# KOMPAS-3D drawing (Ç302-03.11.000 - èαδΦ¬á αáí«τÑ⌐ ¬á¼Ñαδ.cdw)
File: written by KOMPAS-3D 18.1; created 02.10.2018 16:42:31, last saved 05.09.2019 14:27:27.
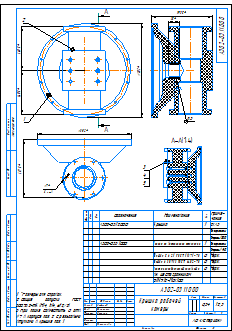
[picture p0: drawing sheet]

Sheet 1: A3, portrait

Document properties: Автор: Милов; Масса: 6.54231; Полное имя файла: ..\А302-01.11.000 - Крышка рабочей камеры.a3d

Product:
- Part/product: (unnamed)
  - Component: Корпус со встроенными стаканами  | designation А302-03.31.000  | pos. 0  | Раздел спецификации: Детали; Примечание: Полипропилен / Стержень @2~140
  - Component: Крышка  | designation А302-03.12.000  | pos. 0  | Раздел спецификации: Детали; Примечание: 2хА3 / Полипропилен / Стержень @2~300
  - Component: Шайба C.6.21 ГОСТ 11371-78  | pos. 0  | Раздел спецификации: Стандартные изделия; Примечание: Нерж.
  - Component: Шайба 6 30Х13 ГОСТ 6402-70  | pos. 0  | Раздел спецификации: Стандартные изделия; Примечание: Нерж.
  - Component: Винт с цилиндрической головкой и  / вн. шестигранником  / DIN 912-М6х100  | pos. 0  | Раздел спецификации: Стандартные изделия; Примечание: Нерж.

Title block, sheet 1: Наименование: Крышка рабочей / камеры; designation: А302-03.11.000; Масса: 6,54; scale: 1:2,5; Количество листов документа: 1; organisation: АО «Астерион»; Форматы листов документа: A3; stored path: \\192.168.87.28\Konstructor_doc\Мембранные насосы\Мембранный электропривод\А302-00.00.000 - ASTRA-302 (МЭ200)\3Д ПВХ\А302-01.11.000 - Крышка рабочей камеры.cdw; Разработал: Лифлянд; Проверил: Борисенко; Т. контр.: Лучихин; Утвердил: Григорьева

Views: Вид 1, Местный разрез 1, Спереди, Проекционный вид 3, Разрез А-А, Вид:1
Referenced files in D:\Мембранные насосы\Мембранный электропривод\А302-00.00.000 - ASTRA-302 (МЭ200)\3Д ПВХ\: А302-01.31.000 - Корпус со встроенными стаканами.m3d, А302-01.12.001 - Крышка.m3d, А302-01.11.000 - Крышка рабочей камеры.a3d, А302-01.12.000 - Крышка.a3d, А302-01.12.000 - Крышка.cdw, А302-01.31.000 - Корпус.a3d, А302-01.31.000 - Корпус.cdw, Втулка резьбовая М6 (шт.) Alutech.m3d
Referenced files in D:\1 ПКИ 3D\ПВХ фитинги, трубы\: Труба PVC-U 50 3,7.m3d
Referenced files in Z:\Мембранные насосы\Мембранный электропривод\А302-00.00.000 - ASTRA-302 (МЭ200)\3Д ПВХ\: А302-01.11.000 - Крышка рабочей камеры.a3d
Referenced files in D:\Мембранные насосы\Мембранный электропривод\А302-00.00.000 - ASTRA-302 (МЭ200)\3Д ПВХ\Отработка\: Отвод ПВХ 90гр 50 арт.GIV050.m3d, Отвод ПВХ 45гр 50 арт.HIV050.m3d
Referenced files in C:\Program Files\ASCON\KOMPAS-3D v18\Libs\PartLib\DATA\VAULT\methods\kompas\3d\: PLib_Washer_1_712.m3d, PLib_Washer_2_712.m3d
Referenced files in D:\2 Стандартные изделия 3D\Винты\Din 912\: Винт DIN 912-М6х100-А2-70.m3d
Referenced files in C:\Program Files\ASCON\KOMPAS-3D v18\Libs\PARTLib\DATA\vault\Methods\Kompas\3D\: PLib_Washer_1_712.m3d, PLib_Washer_2_712.m3d
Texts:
  Крышка
  Корпус
  Отвод ПВХ 90   50 арт.GIV050
  Отвод ПВХ 90@1~ @2~50 арт.GIV050
  Отвод ПВХ 45   50 арт.HIV050
  Отвод ПВХ 45@1~ @2~50 арт.HIV050
  Труба PVC-U 50*3,7
  Корпус со встроенными стаканами
  Полипропилен
  Стержень  300
  2хА3 / Полипропилен / Стержень @2~300
  Стержень  140
  Полипропилен / Стержень @2~140
  Шайба C.6.21 ГОСТ 11371-78
  Шайба
  ГОСТ
  Нерж.
  Шайба 6 30Х13 ГОСТ 6402-70
  Винт с цилиндрической головкой и
  вн. шестигранником
  DIN 912-М6х100
  Винт
  цилиндрической
  головкой
  шестигранником
  DIN
  ART. 9058 ВТУЛКА РЕЗЬБОВАЯ С ВНЕШН. И ВНУТР. РЕЗЬБОЙ M6 / M10 X 14 ММ А1-НЕРЖ
  Труба полипропиленовая 50*4,6
  Винт с цилиндрической головкой / и вн. шестигранником / DIN 912-М6х80-А2-70
Dimensions and other numbers on the sheet: 35; 193,5; 302; 7; 6 отв.; 187,5; 4; 1; 2хА3; 6; 1:2,5; 6,54

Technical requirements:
  *Размеры для справок.
  Общие допуски ГОСТ
  30893.2-mK (H14, h14,  t2/2).
  При пайке совместить 6 отв.
  втулками в крышке поз. 1.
